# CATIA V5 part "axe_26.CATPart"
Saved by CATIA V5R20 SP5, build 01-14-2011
Part number: axe_26
Bounding box of the stored display mesh (mm): x 10 to 16, y 67.046 to 72.954, z 0 to 20
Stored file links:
  F:\Catia_finish\axe_26.CATPart
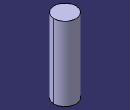
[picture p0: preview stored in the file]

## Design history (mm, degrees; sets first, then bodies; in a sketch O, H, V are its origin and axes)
Body1 (main body)
  Sketch1 on xy-plane, origin (0, 0, 0), H (1, 0, 0), V (0, 1, 0)
    circle A1 centre (13, 70) radius 3
    radius A1 = 3
  Pad1: profile Sketch1, direction (0, 0, 1), length 20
